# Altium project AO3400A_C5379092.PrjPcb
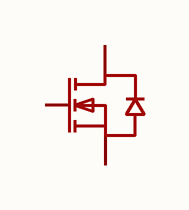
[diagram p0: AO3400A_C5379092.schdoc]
1 sheet, 1 parts. Net scope: global (net labels, ports and power ports of the same name join across sheets).

## Sheet AO3400A_C5379092.schdoc
size 127 x 101 mm

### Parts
Q?  ao3400a_c5379092  [SOT-23-3_L2.9-W1.6-P1.90-LS2.8-BR]  (value not drawn)

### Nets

Not connected (* = marked no-connect by the designer): Q? 1(G) 2(S) 3(D)

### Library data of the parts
Q? = ao3400a_c5379092: 数量:1个N沟道;漏源电压(Vdss):30V;连续漏极电流(Id):5.8A;导通电阻(RDS(on)):20mΩ@10V;耗散功率(Pd):1.4W;阈值电压(Vgs(th)):900mV;; Manufacturer: MSKSEMI(美森科); AddInBom: yes; ModelId: 89cb27a44ab2466697082bb9fd73a7d0; ModelName: SOT-23-3L_L2.9-W1.6-H1.1-LS2.8-P0.95; ModelTransform: 114.173,110.236,0,90,0,0,0,0,0; Number: 1个N沟道; Drain to Source Voltage: 30V; Current - Continuous Drain(Id): 5.8A; Pd - Power Dissipation: 1.4W; Gate Threshold Voltage (Vgs(th)): 900mV; Gate Charge(Qg): 4.1nC@4.5V; Input Capacitance(Ciss): 345pF; Reverse Transfer Capacitance (Crss@Vds): 32pF; Output Capacitance(Coss): 55pF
